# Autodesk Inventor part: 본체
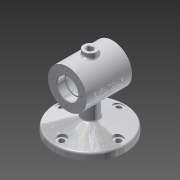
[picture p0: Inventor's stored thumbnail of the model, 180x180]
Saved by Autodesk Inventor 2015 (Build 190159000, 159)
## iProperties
Created: 2018-12
Part Number: 본체
Material: 알루미늄 6061
Document SubType Name: Modeling
Designer: CAD02
Density: 2.7 g/cm^3
Appearance: 알루미늄 - 평지
Mass: 662.303 g
Surface Area: 551.019 cm^2
Volume: 245.298 cm^3
Author: CAD02
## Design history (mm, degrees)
sketch "스케치1"
  geometry: C1 r 55 at (0, 0); 1 further point
  constraints: 1 centre point, 1 coincident
  dimensions: "d0" = 110 diameter of C1
extrude "돌출1" new body sketch "스케치1" distance "d1" = 10; taper "d2" = 0 deg
sketch "스케치2"
  geometry: L1 (-55, 0)-(-55, 10) reference; L2 (-55, 10)-(55, 10) reference; L3 (55, 10)-(55, 0) reference; L4 (55, 0)-(-55, 0) reference; L5 (-55, 10)-(0, 24.737); L6 (0, 24.737)-(0, 10); 1 further point
  constraints: 4 end point, 1 midpoint, 1 vertical
  dimensions: "d3" = 75 deg angle of L1 L5
revolve "회전1" sketch "스케치2" stored, may be unused: angle "d4" = 90 deg
sketch "스케치4"
  geometry: C1 r 55 at (0, 0) reference; C2 r 12 at (0, 0)
  constraints: 1 centre point, 1 coincident
  dimensions: "d5" = 24 diameter of C2
extrude "돌출2" join sketch "스케치4" distance "d6" = 75; taper "d7" = 0 deg
sketch "스케치6"
  geometry: L1 (-12, 21.522)-(-12, 75) reference; L2 (-12, 75)-(12, 75) reference; L3 (12, 75)-(12, 21.522) reference; L4 (12, 21.522)-(55, 10) reference; L5 (55, 10)-(55, 0) reference; L6 (55, 0)-(-55, 0) reference; L7 (-55, 0)-(-55, 10) reference; L8 (-55, 10)-(-12, 21.522) reference; L9 (-35, 75)-(35, 75); L10 (35, 75)-(35, 105); L11 (35, 105)-(-35, 105); L12 (-35, 105)-(-35, 75); 2 further points
  constraints: 8 end point, 3 perpendicular, 2 midpoint, 1 horizontal
  dimensions: "d8" = 70 distance between parallel lines of L10 L12; "d9" = 30 distance between parallel lines of L11 L9
revolve "회전2" sketch "스케치6" stored, may be unused: angle "d10" = 90 deg
sketch "스케치7"
  geometry: L1 (-12, 45)-(-35, 45) reference; L2 (-35, 45)-(-35, 105) reference; L3 (-35, 105)-(35, 105) reference; L4 (35, 105)-(35, 45) reference; L5 (35, 45)-(12, 45) reference; L6 (12, 45)-(12, 21.522) reference; L7 (12, 21.522)-(55, 10) reference; L8 (55, 10)-(55, 0) reference; L9 (55, 0)-(-55, 0) reference; L10 (-55, 0)-(-55, 10) reference; L11 (-55, 10)-(-12, 21.522) reference; L12 (-12, 21.522)-(-12, 45) reference; L13 (-35, 75)-(-23, 75); L14 (-23, 75)-(-23, 90.7); L15 (-23.3, 91)-(-35, 91); L16 (-35, 91)-(-35, 75); L17 (-23, 75)-(-20, 75); L18 (-20, 75)-(-20, 89); L19 (-20, 89)-(-23, 89); L20 (-23, 89)-(-23, 75); L21 (-20, 75)-(20, 75); L22 (20, 75)-(20, 97); L23 (17, 100)-(-17, 100); L24 (-20, 97)-(-20, 75); L25 (20, 75)-(23, 75); L26 (23, 75)-(23, 89); L27 (23, 89)-(20, 89); L28 (20, 89)-(20, 75); L29 (23, 75)-(35, 75); L30 (35, 75)-(35, 91); L31 (35, 91)-(23.3, 91); L32 (23, 90.7)-(23, 75); A1 r 3 centre (-17, 97) between (-17, 100) and (-20, 97); A2 r 3 centre (17, 97) between (20, 97) and (17, 100); A3 r 0.3 centre (-23.3, 90.7) between (-23, 90.7) and (-23.3, 91); A4 r 0.3 centre (23.3, 90.7) between (23.3, 91) and (23, 90.7); 1 further point
  constraints: 40 end point, 10 parallel, 8 point on circle, 8 tangent, 5 horizontal, 5 perpendicular, 4 centre point, 2 equal radius, 1 midpoint
  dimensions: "d11" = 12 distance between parallel lines of L14 L16; "d12" = 16 distance between parallel lines of L13 L15; "d13" = 3 distance between parallel lines of L18 L20; "d14" = 14 distance between parallel lines of L17 L19; "d15" = 40 distance between parallel lines of L22 L24; "d16" = 25 distance between parallel lines of L21 L23; "d17" = 14 distance between parallel lines of L25 L27; "d18" = 3 distance between parallel lines of L26 L28; "d19" = 12 distance between parallel lines of L30 L32; "d20" = 16 distance between parallel lines of L29 L31; "d21" = 3 radius of A1; "d22" = 0.3 radius of A3
revolve "회전3" sketch "스케치7" stored, may be unused: angle "d23" = 90 deg
chamfer "모따기1" distance "d24" = 1; stored, may be unused: second distance "d25" = 2, angle "d26" = 45 deg
sketch "스케치8"
  geometry: C1 r 30 at (0, 0) reference; 2 further points
  constraints: 1 vertical alignment
  dimensions: "d27" = 23 distance of C1.centre point (0, 23)
hole "구멍1" sketch "스케치8" at (0, 23) diameter "d28" = 3.242; stored, may be unused: countersink angle "d32" = 90 deg, drill point angle "d34" = 118 deg; dims "d29" = 8, "d30" = 4, "d31" = 2, "d33" = 10
sketch "스케치9"
  geometry: C1 r 30 at (0, 0) reference; 2 further points
  constraints: 1 vertical alignment
  dimensions: "d38" = 23 distance of point (0, -23) C1.centre
hole "구멍2" sketch "스케치9" at (0, -23) diameter "d39" = 3.242; stored, may be unused: countersink angle "d43" = 90 deg, drill point angle "d45" = 118 deg; dims "d40" = 8, "d41" = 4, "d42" = 2, "d44" = 10
node "작업 평면1"
sketch "스케치10"
  geometry: L1 (30, -35)-(-30, -35) reference; C1 r 10 at (0, 0); 1 further point
  constraints: 1 centre point, 1 coincident
  dimensions: "d50" = 20 diameter of C1; "d51" = 35 distance from line of C1.centre L1
extrude "돌출3" join sketch "스케치10" stored distance "d52" = 75; taper "d53" = 0 deg
sketch "스케치11"
  geometry: C1 r 10 at (0, 0) reference
hole "구멍3" sketch "스케치11" at (0, 0) diameter "d54" = 10; stored, may be unused: countersink angle "d58" = 90 deg, drill point angle "d60" = 118 deg; dims "d55" = 8, "d56" = 4, "d57" = 2, "d59" = 10
fillet "모깎기1" dims "d61" = 3
chamfer "모따기2" distance "d62" = 1; stored, may be unused: second distance "d63" = 2, angle "d64" = 45 deg
sketch "스케치13"
  geometry: C1 r 55 at (0, 0) reference; C2 r 4.5 at (-44, 0); 1 further point
  constraints: 1 centre point, 1 coincident, 1 horizontal alignment
  dimensions: "d65" = 44 distance of C1.centre point (-44, 0); "d66" = 9 diameter of C2
extrude "돌출4" cut sketch "스케치13" stored distance "d67" = 75; taper "d68" = 0 deg
node "작업 평면2"
sketch "스케치16"
  geometry: C1 r 7 at (44, 0); 1 further point
  constraints: 1 centre point, 1 horizontal alignment
  dimensions: "d73" = 14 diameter of C1; "d74" = 44 distance of point (0, 0) C1.centre
extrude "돌출5" cut sketch "스케치16" stored distance "d75" = 14 (= d73); taper "d76" = 0 deg
node "작업 평면3"
sketch "스케치17" dims "d1" = 10, "d2" = 0
  geometry: L1 (-35, 45)-(-35, 105) reference; 2 further points
  constraints: 1 other
  dimensions: "d81" = 35 distance from line of point (0, 75) L1; "d82" = 30 vertical distance of L1.end point (0, 75)
feature "엠보싱1" sketch "스케치17" dims "d83" = 0.5, "d84" = 0
node "솔리드1"
pattern_circular "원형 패턴1" dims angle "d36" = 360 deg
pattern_circular "원형 패턴2" dims angle "d47" = 360 deg
pattern_circular "원형 패턴3" dims angle "d70" = 360 deg
pattern_circular "원형 패턴4" dims angle "d78" = 360 deg
node "절단 모서리 투영1"
node "절단 모서리 투영3"
node "절단 모서리 투영4"
other parameters: "d49" = 112
